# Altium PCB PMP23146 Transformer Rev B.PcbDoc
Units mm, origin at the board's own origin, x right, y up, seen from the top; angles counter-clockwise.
Board outline 35 x 22.3 mm, 6 copper layers (Top Layer, Int1 (Sign), Int2 (Sign), Int3 (Sign), Int4 (Sign), Bottom Layer), stack 2.081 mm thick; 21 components, 16 nets, 60 pads, 32 vias.
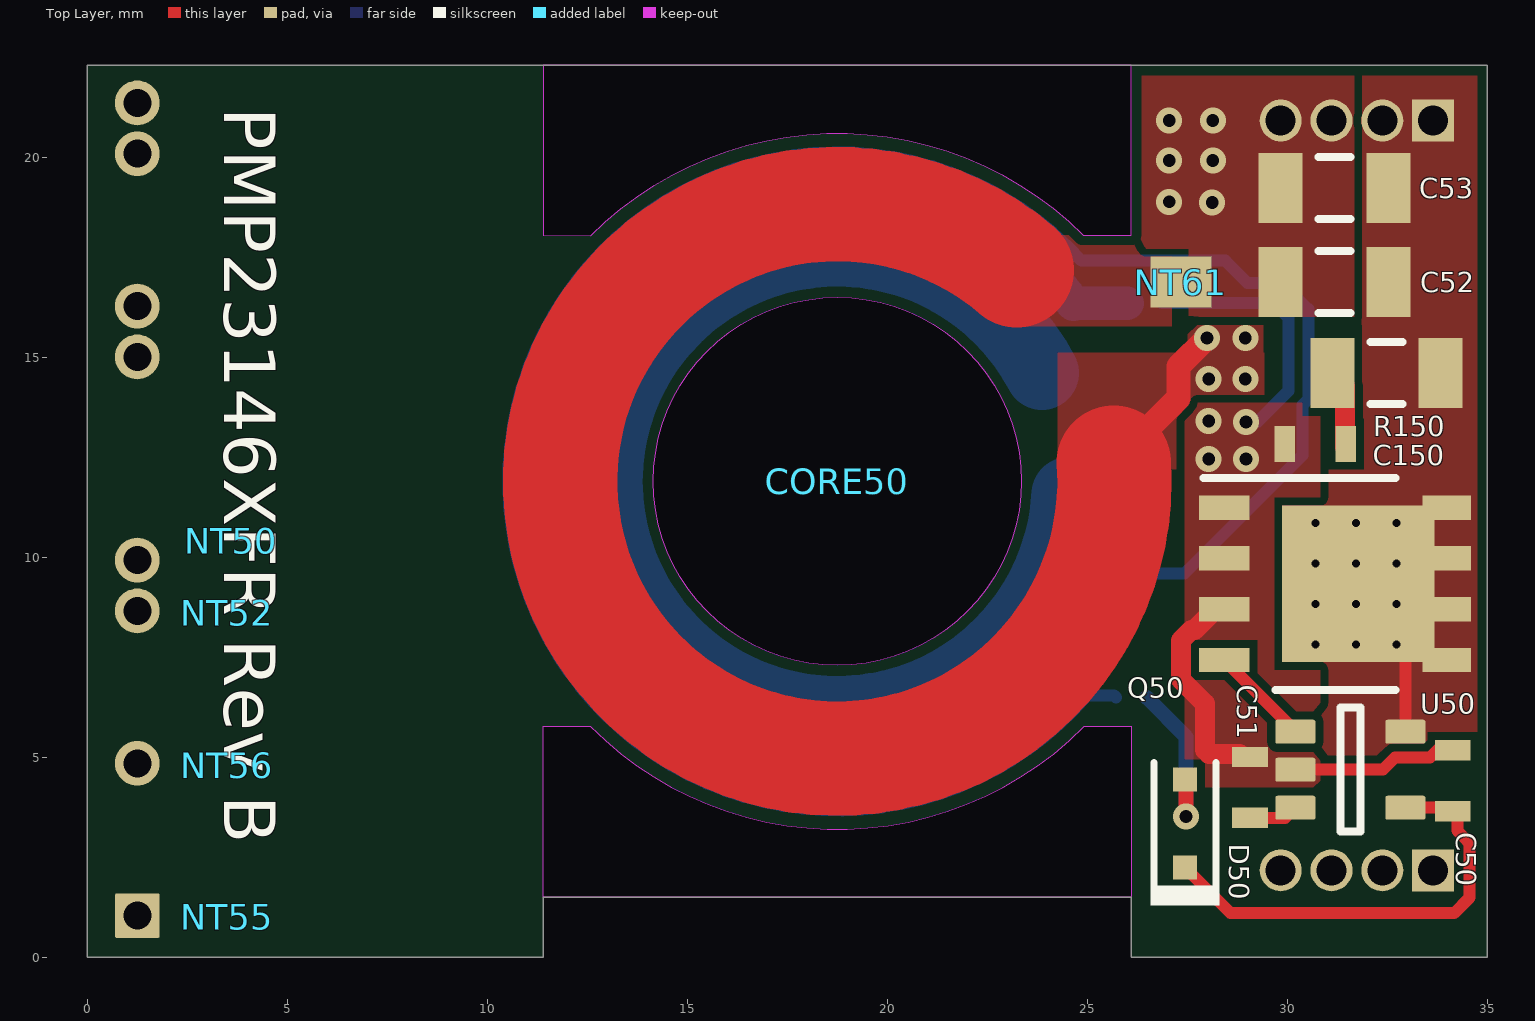
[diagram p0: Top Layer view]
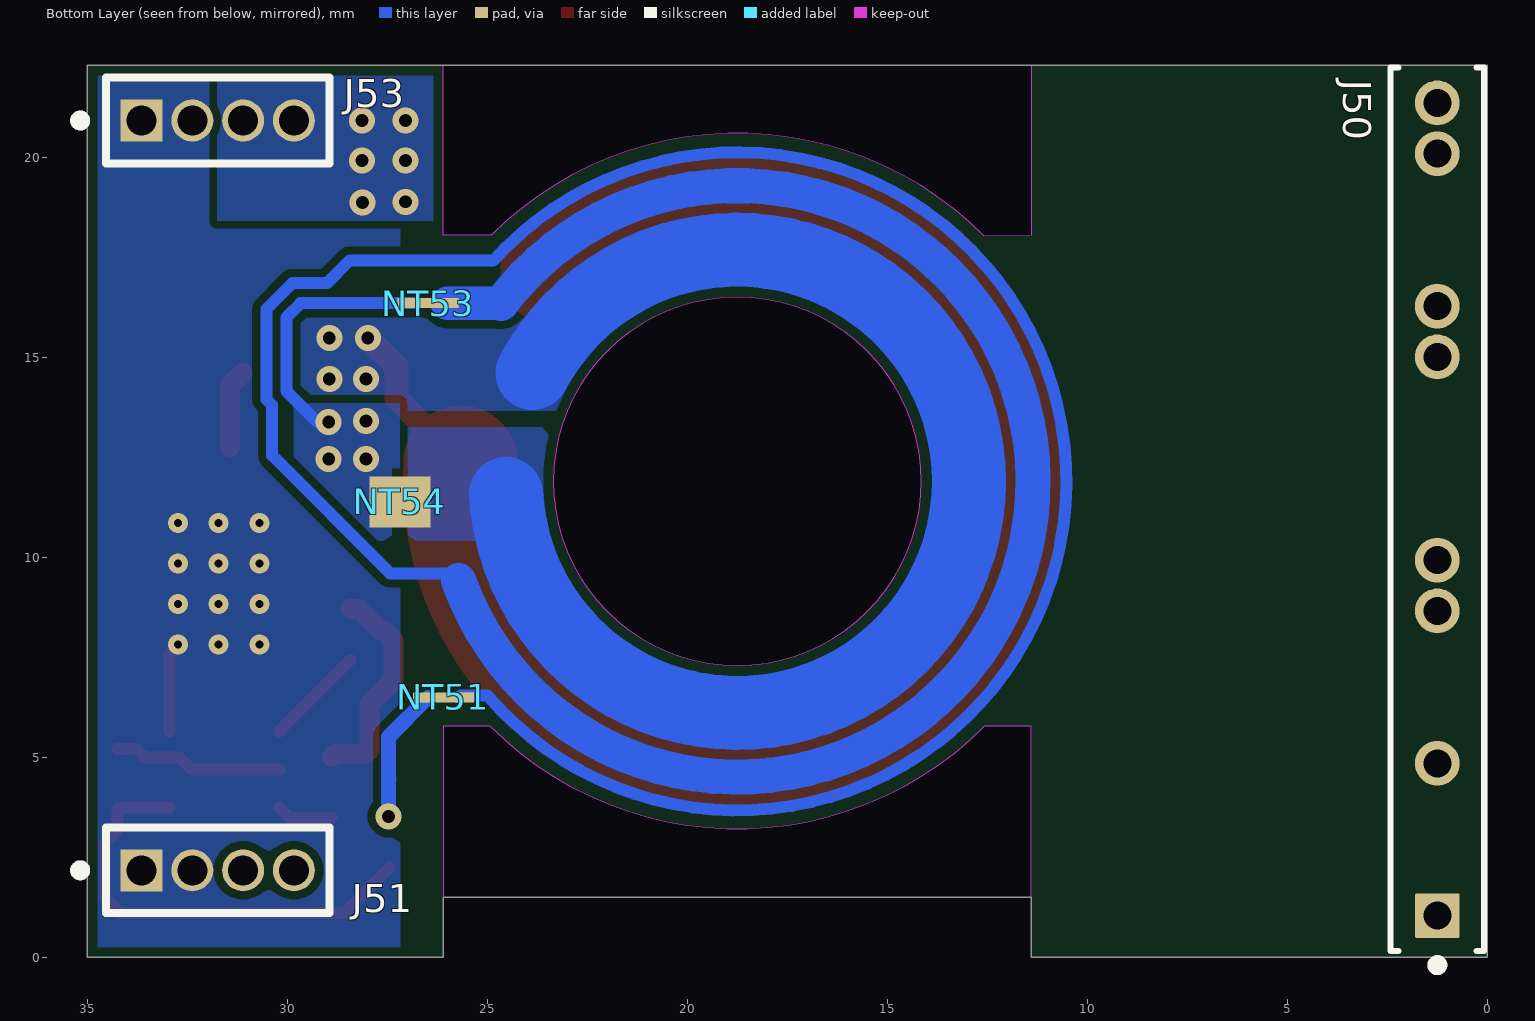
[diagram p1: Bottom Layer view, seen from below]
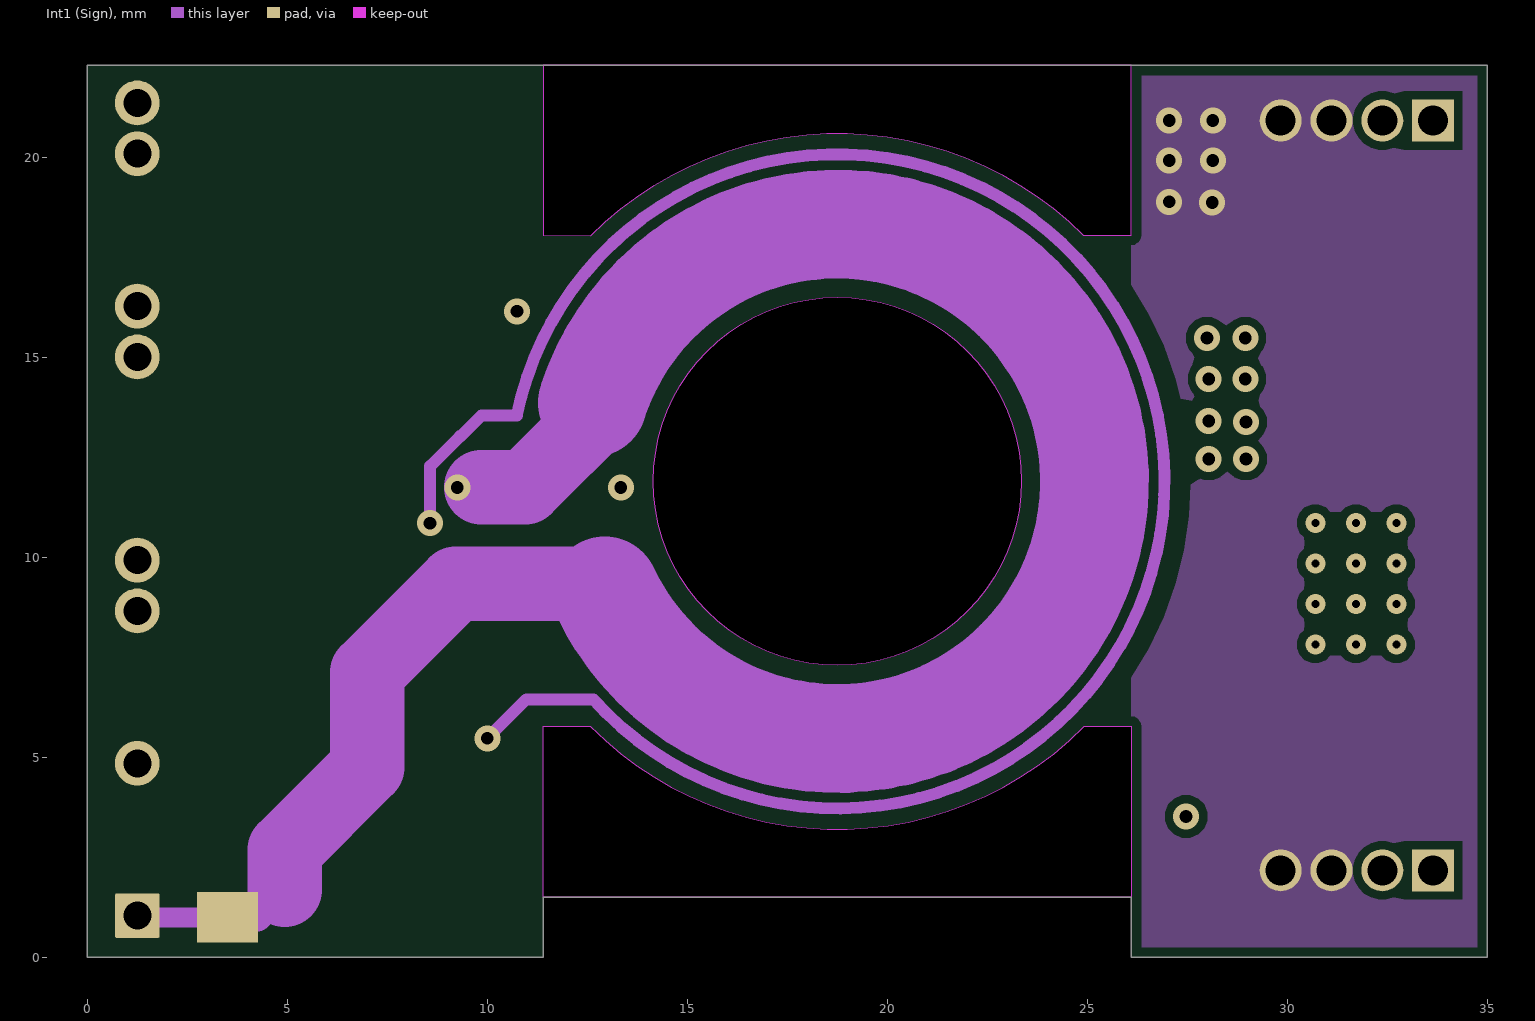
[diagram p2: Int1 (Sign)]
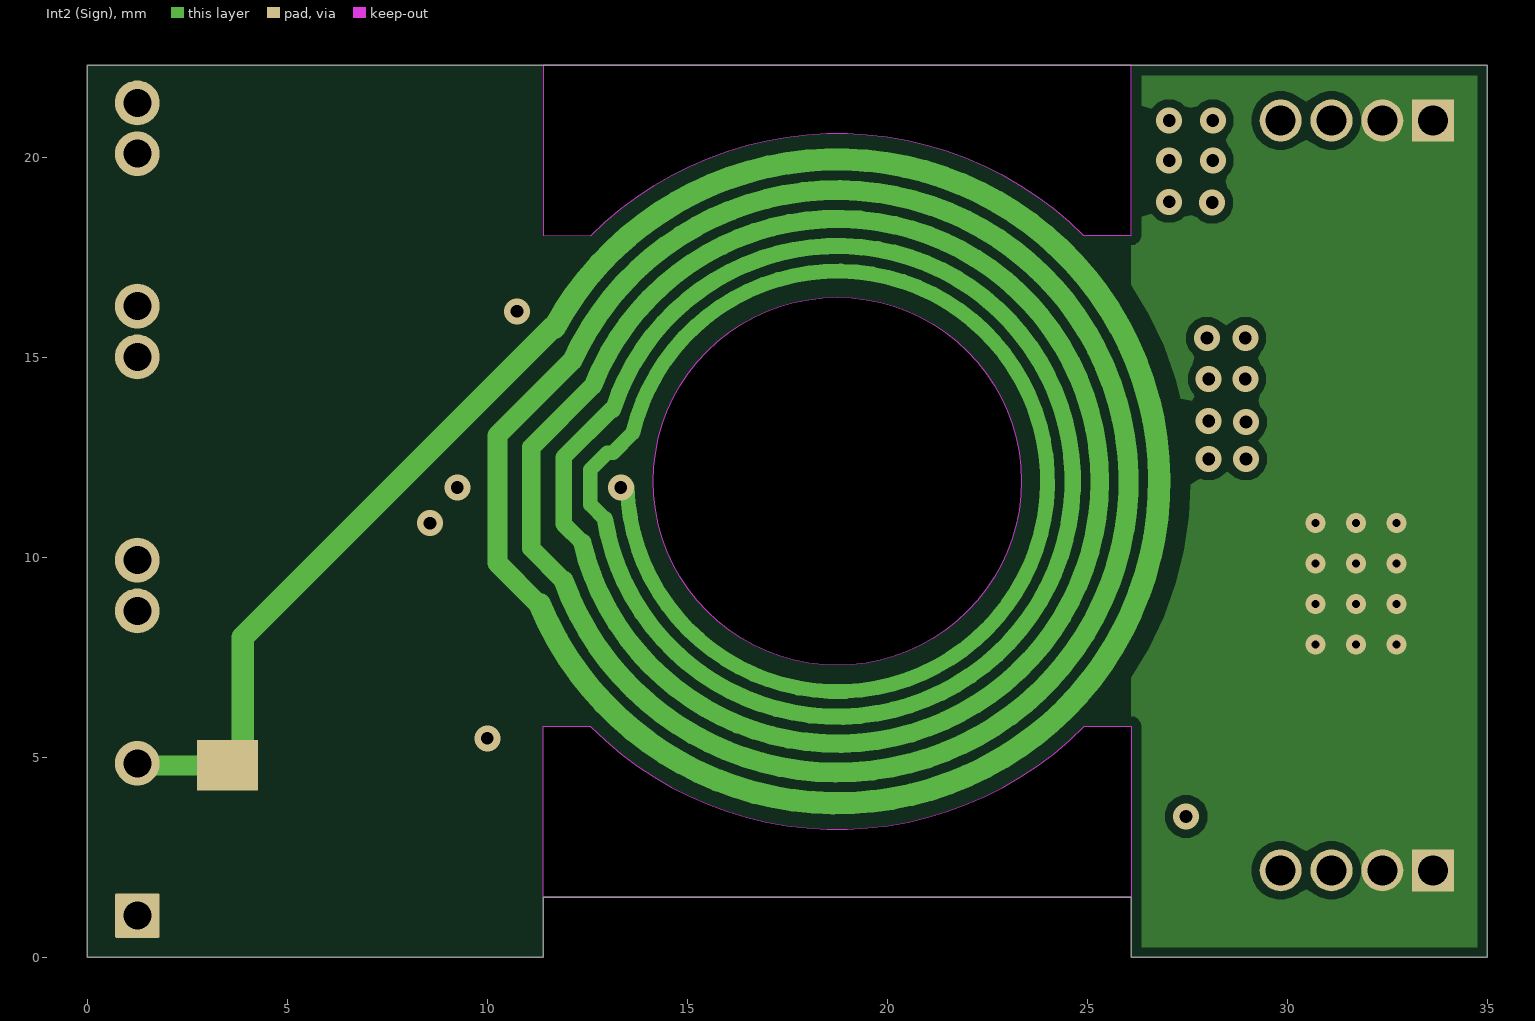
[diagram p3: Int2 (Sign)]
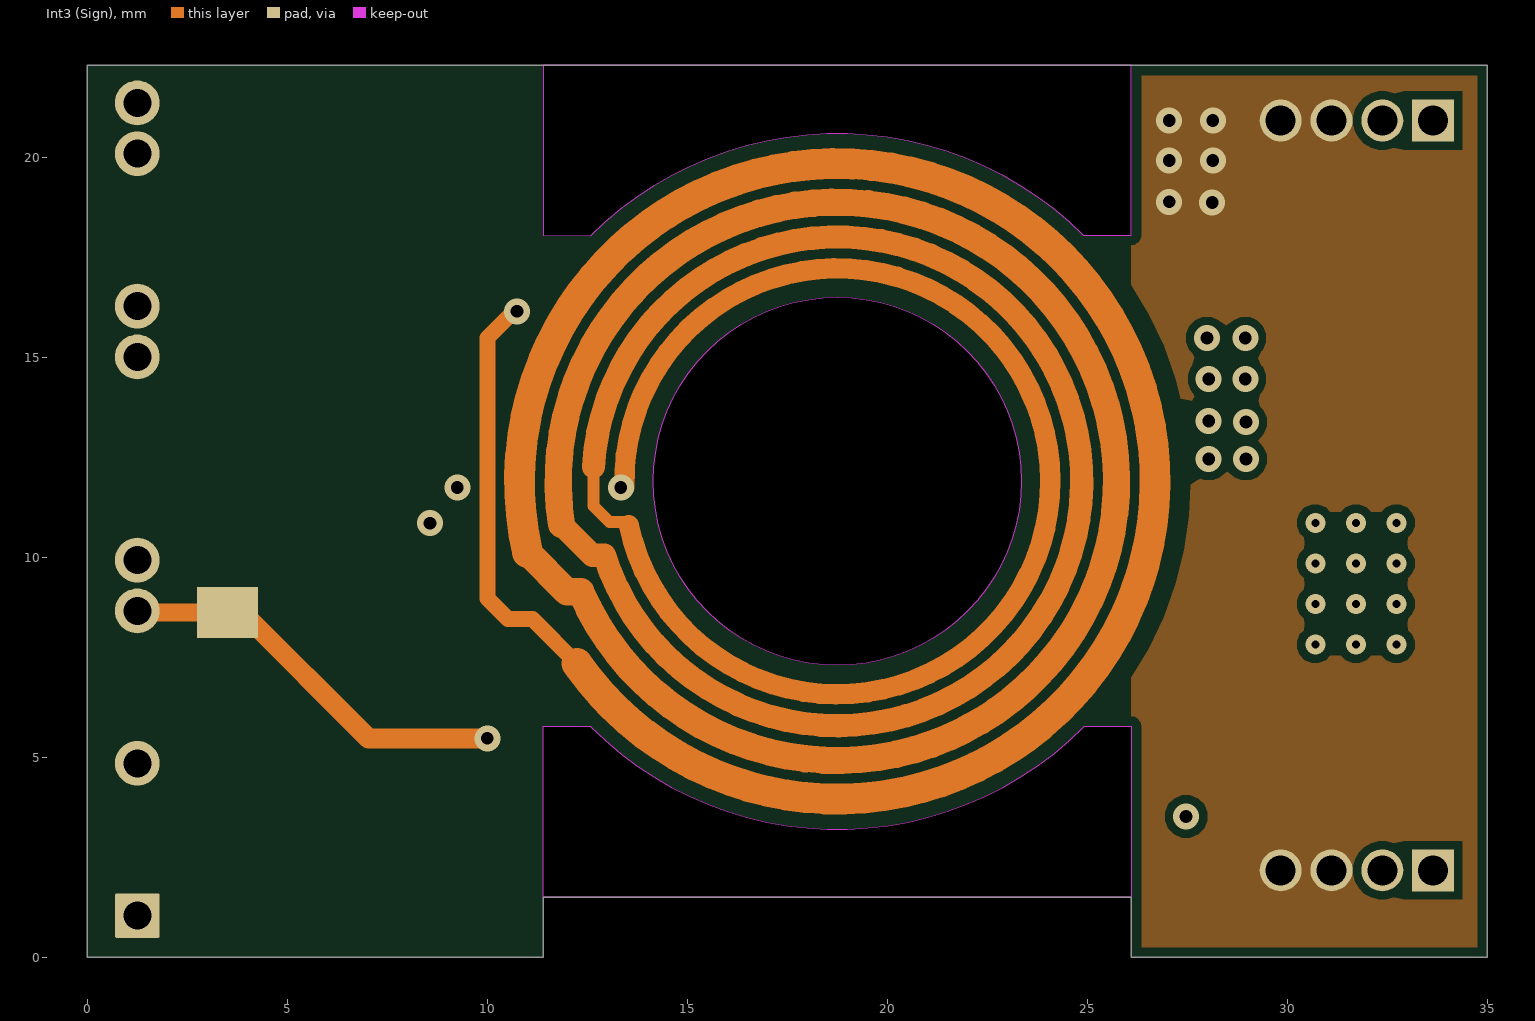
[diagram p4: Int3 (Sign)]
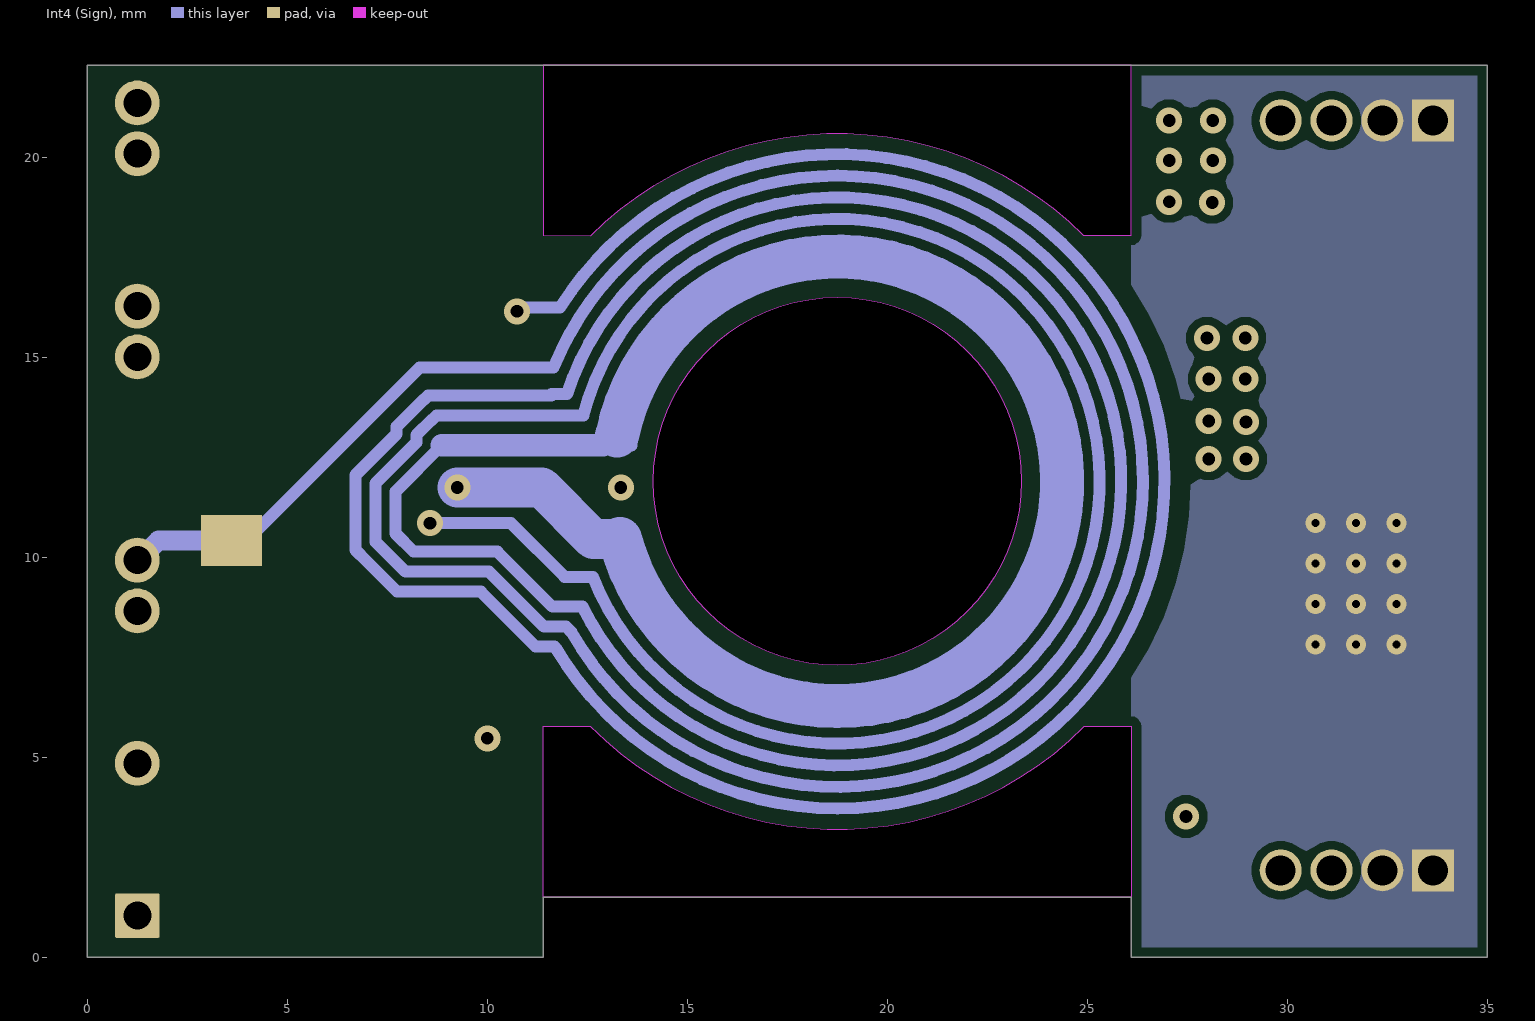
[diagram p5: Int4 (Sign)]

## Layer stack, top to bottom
Top Solder: solder mask 0.0254, SM-001, Dk 4
Top Layer: signal copper 0.07
Dielectric 1: core 0.508, Core-036, Dk 4.6
Dielectric 2: prepreg 0.0584, PP-003, Dk 3.9
Int1 (Sign): signal copper 0.07
Dielectric 3: core 0.1778, Core-022, Dk 4.3
Int2 (Sign): signal copper 0.07
Dielectric 4: prepreg 0.0864, PP-010, Dk 4
Dielectric 5: prepreg 0.0864, PP-010, Dk 4
Int3 (Sign): signal copper 0.07
Dielectric 6: core 0.1778, Core-022, Dk 4.3
Int4 (Sign): signal copper 0.07
Dielectric 7: prepreg 0.0584, PP-003, Dk 3.9
Dielectric 8: core 0.508, Core-036, Dk 4.6
Bottom Layer: signal copper 0.07
Bottom Solder: solder mask 0.0254, SM-001, Dk 4

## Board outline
0,0 0,22.3 35,22.3 35,0 26.1,0 26.1,1.505 11.4,1.505 11.402,0

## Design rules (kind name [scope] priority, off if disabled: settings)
AcuteAngle [All] p1: minimum=5.00000000000000E+0000 checktracksonly=FALSE
AssemblyTestPointUsage [All] p1: valid=2
BoardOutlineClearance BoardOutlineClearance_Pri [InNet('P')] p1: gap=0.4 ignorepadtopadclearanceinfootprint=FALSE
BoardOutlineClearance BoardOutlineClearance_MountingHoles [OnCopper and InComponentClass('Mounting Holes')] p2: gap=0.635 ignorepadtopadclearanceinfootprint=FALSE
BoardOutlineClearance BoardOutlineClearance_Poly [OnCopper and InPoly] p3: gap=0.25 ignorepadtopadclearanceinfootprint=FALSE
BoardOutlineClearance [OnCopper and Not InComponentClass('Logo') and not InComponentClass('FiducialMark') and not InRegion(1000,500,4000,800)] p4: gap=0.25 ignorepadtopadclearanceinfootprint=FALSE
Clearance "Pri To Sec Inner Layers" [InNetClass('Primary') vs InNetClass('Secondary')] p1: gap=0.5 ignorepadtopadclearanceinfootprint=TRUE
Clearance "400V Clearance" [(InNetClass('400V') AND (OnTopLayer Or OnBottomLayer)) vs (InNetClass('Primary LV'))] p2: gap=2.7 ignorepadtopadclearanceinfootprint=FALSE
Clearance Clearance_Keepouts [((IsTrack Or IsArc) And Not InPoly) And IsFree and IsKeepOut vs ((IsTrack Or IsArc) And Not InPoly) And IsFree and IsKeepOut] p3: gap=0 ignorepadtopadclearanceinfootprint=FALSE
Clearance Clearance_Poly [InPolygon] p4: gap=0.203 ignorepadtopadclearanceinfootprint=FALSE except(0: Arc-Hole Track-Hole SMDPad-Hole THPad-Hole Via-Hole Fill-Hole Poly-Hole Region-Hole Text-Hole)
Clearance [All] p5: gap=0.2 ignorepadtopadclearanceinfootprint=TRUE except(0: Arc-Hole Track-Hole SMDPad-Hole THPad-Hole Via-Hole Fill-Hole Poly-Hole Region-Hole Text-Hole)
ComponentClearance ComponentClearance_MountingHoles_FiducialMarks [InComponentClass('Mounting Holes') vs InComponentClass('FiducialMark')] p1: gap=1.27 collisioncheckmode=3 verticalgap=0.254 showdistances=FALSE
ComponentClearance ComponentClearance_Shunt [InComponentClass('Header') vs InComponentClass('Shunt')] p2: gap=0 collisioncheckmode=3 verticalgap=0 showdistances=FALSE
ComponentClearance ComponentClearance_Logo [InComponentClass('Logo')] p3: gap=1.27 collisioncheckmode=3 verticalgap=0.254 showdistances=FALSE
ComponentClearance ComponentClearance_ScrewToNut [(HasFootprint('NY PMS 440 0025 PH')) vs (HasFootprint('Keystone_1902C'))] p4: gap=0.127 collisioncheckmode=3 verticalgap=0.254 showdistances=FALSE
ComponentClearance ComponentClearance_MountingHoles [InComponentClass('Mounting Holes')] p5: gap=6.35 collisioncheckmode=3 verticalgap=2540 showdistances=FALSE
ComponentClearance ComponentClearance_SmallPassives [HasFootprint('0201*') or HasFootprint('0402*') or HasFootprint('0508') or HasFootprint('0603*') or HasFootprint('0612') or HasFootprint('0805*') or HasFootprint('0815*') or HasFootprint('0830*') or HasFootprint('1206*') or HasFootprint('1210*') or HasFootprint('1808*') or HasFootprint('1812*') or HasFootprint('1825*') or HasFootprint('2010*') or HasFootprint('2220*') or HasFootprint('2225*') or HasFootprint('2512*') or HasFootprint('2728*') or HasFootprint('3518*') vs HasFootprint('0201*') or HasFootprint('0402*') or HasFootprint('0508') or HasFootprint('0603*') or HasFootprint('0612') or HasFootprint('0805*') or HasFootprint('0815*') or HasFootprint('0830*') or HasFootprint('1206*') or HasFootprint('1210*') or HasFootprint('1808*') or HasFootprint('1812*') or HasFootprint('1825*') or HasFootprint('2010*') or HasFootprint('2220*') or HasFootprint('2225*') or HasFootprint('2512*') or HasFootprint('2728*') or HasFootprint('3518*')] p6: gap=0.38 collisioncheckmode=3 verticalgap=0.254 showdistances=FALSE
ComponentClearance ComponentClearance_THtoSMT [IsThruComponent vs IsSMTComponent] p7: gap=0.381 collisioncheckmode=3 verticalgap=0.762 showdistances=FALSE
ComponentClearance ComponentClearance_THtoTH [IsThruComponent vs IsThruComponent] p8: gap=0.381 collisioncheckmode=3 verticalgap=0.762 showdistances=FALSE
ComponentClearance [All] p9: gap=0.381 collisioncheckmode=3 verticalgap=0.254 showdistances=FALSE
DiffPairsRouting [All] p1: maxlimit=2.54 minlimit=0.254 mostfreqgap=0.254 toplayer_minwidth=0.381 toplayer_maxwidth=0.381 toplayer_prefwidth=0.381 midlayer1_minwidth=0.381 midlayer1_maxwidth=0.381 midlayer1_prefwidth=0.381 midlayer2_minwidth=0.381 midlayer2_maxwidth=0.381 midlayer2_prefwidth=0.381 midlayer3_minwidth=0.381 midlayer3_maxwidth=0.381 midlayer3_prefwidth=0.381 midlayer4_minwidth=0.381 midlayer4_maxwidth=0.381 midlayer4_prefwidth=0.381 bottomlayer_minwidth=0.381 bottomlayer_maxwidth=0.381 bottomlayer_prefwidth=0.381 maxuncoupledlength=25.4
FabricationTestPointUsage TestPointUsage [All] p1: valid=2 allowmultiple=FALSE
FabricationTestpoint Testpoint [All] p1: side=3 testpointundercomponent=TRUE minsize=1.016 maxsize=2.54 preferedsize=1.524 minholesize=0 maxholesize=1.016 preferedholesize=0.813 testpointgrid=0.025 allowsidetop=TRUE allowsidebottom=TRUE usegrid=TRUE gridtolerance=0
FanoutControl Fanout_LCC [IsLCC] p1: bgadir=Out bgaviamode=Centered fanoutstyle=Auto fanoutdirection=Alternating viagrid=0.025 // Fanout_LCC (Default Rule)
FanoutControl Fanout_BGA [IsBGA] p2: bgadir=Out bgaviamode=Centered fanoutstyle=Auto fanoutdirection=Alternating viagrid=0.025 // Fanout_BGA (Default Rule)
FanoutControl Fanout_Default [All] p4: bgadir=Out bgaviamode=Centered fanoutstyle=Auto fanoutdirection=Alternating viagrid=0.025 // Fanout_Default (Default Rule)
FanoutControl Fanout_Small [(CompPinCount < 5)] p5: bgadir=Out bgaviamode=Centered fanoutstyle=Auto fanoutdirection=OutThenIn viagrid=0.025 // Fanout_Small (Default Rule)
HoleSize [All] p1: absolutevalues=TRUE maxlimit=6.375 minlimit=0.2 maxpercent=80.000 minpercent=20.000
MinimumAnnularRing MinimumAnnularRing_ThermalPadVias [IsVia and InAnyComponent] p1: minimumring=0.15
MinimumAnnularRing [All] p2: minimumring=0.15
MinimumSolderMaskSliver MinimumSolderMaskSliver_Logo [InComponentClass('Logo') vs InComponentClass('Logo')] p1 off: minsoldermaskwidth=0.018
MinimumSolderMaskSliver [All] p2 off: minsoldermaskwidth=0.025
PlaneConnect [All] p1: planeconnectstyle=Direct reliefexpansion=0.254 reliefentries=4 reliefconductorwidth=0.254 reliefairgap=0.254
PolygonConnect [All] p1: connectstyle=Direct reliefconductorwidth=0.381 reliefentries=4 polygonreliefangle="90 Angle" airgapwidth=0.254
RoutingVias ThermalPadVias [IsVia and InAnyComponent] p1: holewidth=0.2 width=0.5 viastyle="Through Hole" minholewidth=0.2 minwidth=0.5 maxholewidth=0.33 maxwidth=0.6
RoutingVias [All] p2: holewidth=0.406 width=0.864 viastyle="Through Hole" minholewidth=0.2 minwidth=0.65 maxholewidth=1.016 maxwidth=1.651
SilkToBoardRegionClearance [Not ((IsComment or IsDesignator) And (Hide <> 'False')) and not InRegion(1000,500,4000,800)] p1:
SilkToSilkClearance SilkToSilkClearance_Pb-FreeLogo [(HasFootprint('Pb-Free_Overlay_Medium') OR HasFootprint('Pb-Free_Overlay_Small')) vs (HasFootprint('Pb-Free_Overlay_Medium') OR HasFootprint('Pb-Free_Overlay_Small'))] p1: silktosilkclearance=0
SilkToSilkClearance [All] p2: silktosilkclearance=0.025
SilkToSolderMaskClearance SilkToComponentPadClearance [IsPad and InAnycomponent] p1: minsilkscreentomaskgap=0 clearancetoexposedcopper=TRUE
SilkToSolderMaskClearance "Silk to Solder Mask Opening" [All] p2: minsilkscreentomaskgap=0 clearancetoexposedcopper=FALSE
SolderMaskExpansion [All] p1: expansion=0.05 istentingtop=FALSE
Width [All] p1: maxlimit=4 minlimit=0.152 preferedwidth=0.254 checkconnectedcopper=TRUE
15 further rules are at their usual default settings.

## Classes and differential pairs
net class Secondary: ISNS S12V
net class Primary: NetNT50_2 NetNT55_2
component class Header: J51 J53

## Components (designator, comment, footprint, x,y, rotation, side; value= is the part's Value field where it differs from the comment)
C50 "GRM188R61E105KA12D" 0603S 34.14,4.415 r90 top value=1uF
C51 "GRM188R61C225KAAD" 0603S 29.067,4.248 r90 top value=2.2uF
C52 "C3216X5R1V226M160AC" 1206_180L 31.175,16.881 r0 top value=22uF
C53 "C3216X5R1V226M160AC" 1206_180L 31.175,19.229 r0 top value=22uF
C150 "GRM1885C2A101JA01D" 0603S 30.699,12.833 r180 top value=100pF
CORE50 "70uH" PCBComponent_1 18.75,11.9 r0 top
D50 "BAS20HT1G" SOD-323 27.44,3.35 r90 top value=200V
J50 "TMS-117-01-L-S" FP-GRPB171VWVN-RC_HDR17-MFG 1.25,11.2 r90 bottom
J51 "TMS-104-01-L-S" Sullins_GRPB041VWVN-RC 31.74,2.175 r180 bottom
J53 "TMS-104-01-L-S" Sullins_GRPB041VWVN-RC 31.74,20.92 r180 bottom
NT50 "Net-Tie" Net-Tie_50milWide_30milLong#1 3.6,10.418 r0 top net-tie
NT51 "Net-Tie" Net-Tie_10milWide_30milLong 26.1,6.498 r180 bottom net-tie
NT52 "Net-Tie" Net-Tie_50milWide_30milLong#2 3.5,8.62 r180 top net-tie
NT53 "Net-Tie" Net-Tie_10milWide_30milLong 26.481,16.355 r0 bottom net-tie
NT54 "Net-Tie" Net-Tie_50milWide_30milLong#3 27.183,11.386 r180 bottom net-tie
NT55 "Net-Tie" Net-Tie_50milWide_30milLong#4 3.5,1 r0 top net-tie
NT56 "Net-Tie" Net-Tie_50milWide_30milLong#5 3.5,4.8 r180 top net-tie
NT61 "Net-Tie" Net-Tie_50milWide_30milLong#3 27.336,16.881 r180 top net-tie
Q50 "FDMS86200" PowerPAK_SO-8 31.207,9.339 r0 top value=100V
R150 "ERJ-8ENF14R0V" 1206L 32.474,14.604 r0 top value=14.0
U50 "UCC24612-1DBVR" DBV0005A_N 31.575,4.69 r0 top

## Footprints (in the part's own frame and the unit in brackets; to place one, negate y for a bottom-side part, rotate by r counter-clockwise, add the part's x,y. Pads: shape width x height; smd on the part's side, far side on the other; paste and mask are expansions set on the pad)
0603S [mil]
  rect 20x35 smd: 1(-30,0) 2(30,0)
  body extent -34,-19 34,19, height 39
1206_180L [mm] "1206_180"
  rect 1.1x1.75 smd: 1(-1.35,0) 2(1.35,0)
  silkscreen extent -0.4,-0.77 0.4,0.77, body extent -1.75,-0.95 1.75,0.95, height 1.8
1206L [mm] "1206 from SM-752 data"
  rect 1.1x1.75 smd: 1(-1.35,0) 2(1.35,0)
  silkscreen extent -0.4,-0.77 0.4,0.77, body extent -1.7,-0.9 1.7,0.9, height 1.35
DBV0005A_N [mm] "SOT23, 5-Leads, Body 2.9x1.6mm, Pitch 0.95mm, Lead Span 2.8mm, IPC Medium Density"
  rrect17% 1x0.6 smd: 1(-1.375,0.95) 2(-1.375,0) 3(-1.375,-0.95) 4(1.375,-0.95) 5(1.375,0.95)
  silkscreen extent -0.25,-1.55 0.25,1.55, body extent -1.42,-1.46 1.42,1.46, height 1.09
FP-GRPB171VWVN-RC_HDR17-MFG [mm]
  rrect9% 1.12x1.12 hole 0.7 paste-1000 mask+0: 1(-10.16,0)
  round 1.12 hole 0.7 paste-1000 mask+0: 4(-6.35,0) 7(-2.54,0) 8(-1.27,0) 12(3.81,0) 13(5.08,0) 16(8.89,0) 17(10.16,0)
  silkscreen extent -11.52,-1.17 11.04,1.17, body extent -10.79,-1.07 10.79,1.07, height 4.4
Net-Tie_10milWide_30milLong [mil] "10mil net tie, no solder mask opening, no solder paste"
  rect 30x10 smd paste-5 mask-5: 1(-15,0) 2(15,0)
Net-Tie_50milWide_30milLong#1 [mil] "50mil net tie, no solder mask opening, no solder paste"
  rect 30x50 on Mid4 paste-20 mask-20: 1(-15,0) 2(15,0)
Net-Tie_50milWide_30milLong#2 [mil] "50mil net tie, no solder mask opening, no solder paste"
  rect 30x50 on Mid3 paste-20 mask-20: 1(-15,0) 2(15,0)
Net-Tie_50milWide_30milLong#3 [mil] "50mil net tie, no solder mask opening, no solder paste"
  rect 30x50 smd paste-20 mask-20: 1(-15,0) 2(15,0)
Net-Tie_50milWide_30milLong#4 [mil] "50mil net tie, no solder mask opening, no solder paste"
  rect 30x50 on Mid1 paste-20 mask-20: 1(-15,0) 2(15,0)
Net-Tie_50milWide_30milLong#5 [mil] "50mil net tie, no solder mask opening, no solder paste"
  rect 30x50 on Mid2 paste-20 mask-20: 1(-15,0) 2(15,0)
PCBComponent_1 [mm]
  Top Layer pour cut-out: 0,-4.6 -1.76,-4.25 -3.253,-3.253 -4.25,-1.76 -4.6,0 -4.6,0 -4.25,1.76 -3.253,3.253 -1.76,4.25 0,4.6 0,4.6 1.76,4.25 3.253,3.253 4.25,1.76 4.6,0 4.6,0 4.25,-1.76 3.253,-3.253 1.76,-4.25 0,-4.6
  Keep-Out Layer board cut-out: -7.348,6.152 -6.164,6.14 -3.341,8.033 -0.009,8.7 3.325,8.039 6.152,6.152 6.152,6.152 7.35,6.152 7.35,10.4 -7.35,10.4
  Keep-Out Layer board cut-out: -7.35,-10.4 -7.35,-6.127 -6.176,-6.127 -3.345,-8.031 0,-8.7 3.345,-8.031 6.176,-6.127 6.176,-6.127 7.35,-6.127 7.35,-10.4
  Keep-Out Layer board cut-out: 0,-4.6 -1.76,-4.25 -3.253,-3.253 -4.25,-1.76 -4.6,0 -4.6,0 -4.25,1.76 -3.253,3.253 -1.76,4.25 0,4.6 0,4.6 1.76,4.25 3.253,3.253 4.25,1.76 4.6,0 4.6,0 4.25,-1.76 3.253,-3.253 1.76,-4.25 0,-4.6
PowerPAK_SO-8 [mil] "Vishay PowerPAK SO-8, Body 5.3x6.0mm (max), Pitch 1.27mm, IPC Medium Density"
  rect 50x24 smd mask+2.99: 1(-109.5,75) 2(-109.5,25) 3(-109.5,-25) 4(-109.5,-75)
  rect 48x24 smd mask+2.99: 5(109.5,-75) 8(109.5,75)
  rect 48x24 smd paste-12 mask+2.99: 6(109.5,-25) 7(109.5,25)
  rect 150x154 smd paste-75 mask+2.99: 9(22.5,0)
  silkscreen extent -130,-104 59,104, body extent -121,-102 121,102, height 43
SOD-323 [mm] "NXP recommended land pattern"
  rect 0.6x0.6 smd paste-0.05: 1(-1.1,0) 2(1.1,0)
  silkscreen extent -2.06,-0.86 1.53,0.86, body extent -1.3,-0.67 1.3,0.68, height 1.1
Sullins_GRPB041VWVN-RC [mm] "TH, Header, 1.27 mm, 4x1, Straight"
  rect 1.05x1.05 hole 0.75: 1(-1.905,0)
  round 1.05 hole 0.75: 2(-0.635,0) 3(0.635,0) 4(1.905,0)
  silkscreen extent -3.54,-1.07 2.79,1.07, body extent -2.79,-1.07 2.79,1.07, height 4.3

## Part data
C50: library part CMP-0007343-5, "CAP, CERM, 1 uF, 25 V, +/- 10%, X5R, 0603", Cap_Case=0603, Manufacturer=MuRata, Supplier Part Number 1=490-3897-1-ND, TempCo=X5R, Tolerance_%=10%, Value1=Unknown, Value2=25V, ValueDisplayed=1uF
C51: library part CMP-0007338-5, "CAP, CERM, 2.2 uF, 16 V, +/- 10%, X5R, 0603", Cap_Case=0603, Manufacturer=MuRata, TempCo=X5R, Tolerance_%=10%, Value1=Unknown, Value2=16V, ValueDisplayed=2.2uF
C52 C53: library part CMP-0008667-2, "CAP, CERM, 22 uF, 35 V, +/- 20%, X5R, 1206", Cap_Case=1206_180, Manufacturer=TDK, Supplier Part Number 1=445-8045-1-ND, TempCo=X5R, Tolerance_%=20%, Value1="0.002398 ohm", Value2=35V, ValueDisplayed=22uF
C150: library part CMP-0007237-4, "CAP, CERM, 100 pF, 100 V, +/- 5%, C0G/NP0, 0603", Cap_Case=0603, Manufacturer=MuRata, Supplier Part Number 1=490-1351-1-ND, TempCo=C0G/NP0, Tolerance_%=5%, Value1=Unknown, Value2=100V, ValueDisplayed=100pF
CORE50: library part Component_1, "EQ20 + I core set, N49 material, gapped to 70uH", Alternate Manufacturer=-, Manufacturer=EPCOS, PartNumber="B66483G0000X149 + B66483K0000X149"
D50: library part CMP-0029150-2, "Diode, Switching, 200 V, 0.2 A, AEC-Q101, SOD-323", Manufacturer="ON Semiconductor", Value1=0.2A, Value2=1.25V
J50: library part CMP-BK1, "Connector Header Through Hole 17 position 0.050\" (1.27mm)", Current_A=1A, Digikey Part Number=GRPB171VWVN-RC-ND, Manufacturer=Samtec, Operating Temperature Range="-40°C to +105°C", Part Number=GRPB171VWVN-RC
J51 J53: library part CMP-0054569-1, "Header, 50mil, 4x1, Gold, TH", Manufacturer=Samtec, Supplier Part Number 1=S9014E-04-ND
NT50 NT52 NT55 NT56: library part CMP-0078142-4, "Single point connection between nets.", Manufacturer=N/A
NT51 NT53 NT54 NT61: library part CMP-0078142-1, "Single point connection between nets.", Manufacturer=N/A
Q50: library part CMP-0000985-1, "MOSFET, N-CH, 150 V, 35 A, PQFN08A", Alternate Manufacturer=None, Manufacturer="Fairchild Semiconductor", Supplier Part Number 1=FDMS86105CT-ND, Value1=0.03, Value2="4.2 nC"
R150: library part CMP-0017368-3, "RES, 14.0, 1%, 0.25 W, AEC-Q200 Grade 0, 1206", Manufacturer=Panasonic, Power_W=250mW, Supplier Part Number 1=P14.0FCT-ND, TempCo="100 ppm/C", Tolerance_%=1%, Value2=0.25W, Value_Code=14R0, ValueDisplayed=14.0
U50: library part CMP-0013050-3, "High-Frequency Multi-Mode Synchronous Rectifier Controller, DBV0005A (SOT-23-5)", Alternate Manufacturer="Texas Instruments", Alternate PartNumber=UCC24612-1DBVT

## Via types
v1: diameter 0.65, hole 0.32, Top Layer to Bottom Layer, 15 vias
v2: diameter 0.5, hole 0.2, Top Layer to Bottom Layer, 12 vias
v3: diameter 0.65, hole 0.32, Int1 (Sign) to Int4 (Sign), 5 vias

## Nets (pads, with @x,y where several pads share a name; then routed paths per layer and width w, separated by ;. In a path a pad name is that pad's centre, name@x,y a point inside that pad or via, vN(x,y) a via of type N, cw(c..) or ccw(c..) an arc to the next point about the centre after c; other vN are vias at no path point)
ISNS: C52.1 C53.1 J51.3 J51.4 J53.3 J53.4 NT61.1
  other v1: 28.121,18.867 27.047,18.889 27.047,19.923 28.137,19.923 27.047,20.92 28.137,20.92
NetC50_1: C50.1 D50.1 U50.4 | length 11.4
  Top Layer w0.3: D50.1 28.585,1.105 34.169,1.105 34.555,1.491 34.555,2.859 34.426,2.988 34.25,3.164 34.25,3.688 34.199,3.74 U50.4
NetC50_2: C50.2 C51.2 C150.2 NT53.2 NT54.1 Q50.1 Q50.2 Q50.3 U50.2 | length 15.9
  Top Layer w0.3: U50.2 32.389,4.69 32.689,4.99 33.565,4.99 33.788,5.212 C50.2@34.25,5.212
  Top Layer w0.5: Q50.3 28.201,8.704 27.685,8.189 27.604,8.189 27.34,7.925 27.34,6.943 27.943,6.34 27.943,5.183 28.044,5.082 28.804,5.082 C51.2@28.877,5.009
  Bottom Layer w0.3: NT53.2 29.667,16.355 30.026,15.996 30.026,14.158 v1@29.25,13.382
  other v1: 28.034,12.456 28.964,12.456 28.964,13.382 28.034,13.406
NetC51_1: C51.1 U50.3 | length 1.4
  Top Layer w0.3: C51.1@28.877,3.485 29.945,3.485 U50.3
NetC150_1: C150.1 R150.1 | length 2
  Top Layer w0.5: R150.1 31.437,14.291 C150.1@31.437,12.755
NetD50_2: D50.2 NT51.1 | length 4.3
  Top Layer w0.37: D50.2 27.47,4.419 v1(27.47,3.523)
  Bottom Layer w0.37: NT51.1 27.47,5.508 v1(27.47,3.523)
NetNT50_2: NT50.2 NT52.1 | length 164
  Int1 (Sign) w0.3: v3(8.567,10.852) 8.567,12.257 8.57,12.26 8.57,12.279 9.32,13.029 9.339,13.029 9.852,13.542 10.736,13.542 ; v3(10,5.476) 10.975,6.451 12.649,6.451 ccw(c18.75,11.9) 10.736,13.542 ; 10.746,13.54 10.738,13.54 10.736,13.542
  Int3 (Sign) w0.5: NT52.1 7.025,5.476 v3(10,5.476)
  Int4 (Sign) w0.3: NT50.2 8.305,14.742 11.658,14.742 cw(c18.75,11.9) 12.105,8.13 11.97,8.265 11.417,8.265 10.043,9.64 7.953,9.64 7.204,10.389 7.204,11.851 8.229,12.876 8.229,13.06 8.598,13.429 8.613,13.429 8.723,13.54 12.398,13.54 cw(c18.75,11.9) 12.64,9.512 11.932,9.512 10.592,10.852 v3(8.567,10.852)
NetNT51_2: NT51.2 NT53.1 | length 96.9
  Bottom Layer w0.3: 25.717,9.421 25.896,9.6 27.432,9.6 30.38,12.548 30.38,13.805 30.526,13.951 30.526,16.203 29.874,16.855 29.008,16.855 28.448,17.415 24.852,17.415 ccw(c18.75,11.9) 24.993,6.546 25.671,6.546 NT51.2
  Bottom Layer w0.84: 24.658,16.355 NT53.1@26,16.355
  Bottom Layer w0.88: 24.654,16.352 ccw(c18.75,11.9) 25.717,9.421
NetNT54_2: NT54.2 NT61.2 | length 76.1
  Top Layer w0.37: 25.664,12.367 25.664,13.158
  Top Layer w0.6: 25.664,12.367 27.274,13.976 27.274,14.768 v1(27.989,15.483)
  Top Layer w2.86: 23.24,17.179 ccw(c18.75,11.9) 25.664,12.367
  Bottom Layer w1.85: 23.87,14.604 ccw(c18.75,11.9) 24.531,11.584
  other v1: 28.034,14.461 28.95,14.461 28.95,15.483
NetNT55_2: NT55.2 NT56.1 | length 595.6
  Int1 (Sign) w0.5: NT55.2 NT55.2@4.25,1
  Int1 (Sign) w0.7: NT55.2@4.25,1 4.935,1.685
  Int1 (Sign) w1.86: 4.935,1.685 4.935,2.685 7,4.75 7,7.129 9.21,9.339 13.324,9.339 ; 9.85,11.749 10.95,11.749 12.935,13.735 13.037,13.735
  Int1 (Sign) w2.72: 12.628,13.866 cw(c18.75,11.9) 12.935,9.155
  Int2 (Sign) w0.37: 12.941,10.956 12.574,11.324 12.574,12.189 13,12.616 13.142,12.616 13.636,13.11 cw(c18.75,11.9) v3@13.497,11.748 ; v3@13.225,11.748 13.334,11.748 v3(13.336,11.749)
  Int2 (Sign) w0.41: 12.371,10.37 11.907,10.834 11.907,12.5 13.092,13.685 13.142,13.685 cw(c18.75,11.9) 12.941,10.956
  Int2 (Sign) w0.46: 11.907,9.416 11.1,10.222 11.1,12.751 12.642,14.292 cw(c18.75,11.9) 12.371,10.37
  Int2 (Sign) w0.5: 11.312,8.822 11.289,8.822 10.25,9.861 10.25,13.044 12.126,14.92 cw(c18.75,11.9) 11.907,9.416
  Int2 (Sign) w0.56: NT56.1 3.881,8 11.614,15.733 ; 11.312,8.822 ccw(c18.75,11.9) 11.671,15.733
  Int3 (Sign) w0.3: v3@10.667,16.15 v3(10.746,16.15) ; 12.651,12.267 12.651,11.286 13.049,10.888 13.459,10.888 13.538,10.809
  Int3 (Sign) w0.4: v3@10.667,16.15 10,15.483 10,8.975 10.523,8.452 11.132,8.452 12.242,7.343
  Int3 (Sign) w0.51: v3@13.427,11.752 cw(c18.75,11.9) 13.538,10.809
  Int3 (Sign) w0.58: 11.853,10.825 12.628,10.051 12.927,10.051 ccw(c18.75,11.9) 12.651,12.267
  Int3 (Sign) w0.68: 11.006,10.123 11.99,9.14 12.339,9.14 ccw(c18.75,11.9) 11.853,10.825
  Int3 (Sign) w0.77: 11.006,10.123 cw(c18.75,11.9) 12.242,7.343
  Int4 (Sign) w0.3: 8.859,12.799 7.704,11.644 7.704,10.596 8.16,10.14 10.25,10.14 11.625,8.765 12.38,8.765 ccw(c18.75,11.9) 11.996,14.089 11.605,14.089 11.605,14.04 8.516,14.04 8.406,13.929 8.391,13.929 7.729,13.267 7.729,13.084 6.704,12.058 6.704,10.182 6.986,9.899 7.182,9.704 7.482,9.404 7.746,9.14 9.836,9.14 11.21,7.765 11.68,7.765 11.71,7.735 ccw(c18.75,11.9) 11.822,16.249 10.845,16.249 v3(10.746,16.15) ; 12.895,12.799 12.904,12.79 13.607,12.79
  Int4 (Sign) w0.56: 8.859,12.799 12.895,12.799
  Int4 (Sign) w1: v3(9.25,11.748) 11.359,11.748 12.651,10.456 13.319,10.456
  Int4 (Sign) w1.1: 13.248,13.044 cw(c18.75,11.9) 13.319,10.456
NetQ50_4: Q50.4 U50.1 | length 2.5
  Top Layer w0.3: Q50.4 30.2,5.659 U50.1
PWRGND: J50.7 NT52.2 | length 1.9
  Int3 (Sign) w0.46: J50.7@1.25,8.62 NT52.2
S12V: C52.2 C53.2 J51.1 J51.2 J53.1 J53.2 Q50.5 Q50.6 Q50.7 Q50.8 Q50.9 R150.2 U50.5 | length 2.3
  Top Layer w0.3: v2(32.731,7.815) 32.95,7.596 U50.5
  other v2: 30.699,7.815 31.715,7.815 30.699,8.831 31.715,8.831 32.731,8.831 30.699,9.847 31.715,9.847 32.731,9.847 30.699,10.863 31.715,10.863 32.731,10.863
VAUX: J50.8 NT50.1 | length 2.1
  Int4 (Sign) w0.5: J50.8@1.25,9.89 1.778,10.418 NT50.1@3.119,10.418
VDCIN: J50.1 NT55.1 | length 1.9
  Int1 (Sign) w0.5: J50.1@1.25,1 NT55.1
VSWN: J50.4 NT56.2 | length 1.9
  Int2 (Sign) w0.5: J50.4@1.26,4.8 NT56.2
  Int2 (Sign) w0.7: J50.4@1.25,4.81 J50.4@1.26,4.8
pads on no net: J50.12 J50.13 J50.16 J50.17

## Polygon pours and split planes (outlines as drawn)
NetC50_2 on Top Layer "TOP_LAYER_NETC50_2_P000" (solid, remove dead copper, pour order 0): 27.432,4.247 30.824,4.247 30.824,13.86 27.432,13.86
NetNT54_2 on Top Layer "TOP_LAYER_NETNT54_2_P014" (solid, remove dead copper, pour order 14): 27.505,13.108 29.398,13.108 29.398,15.907 27.505,15.907
NetNT54_2 on Top Layer "TOP_LAYER_NETNT54_2_P005" (solid, remove dead copper, pour order 5): 23.041,15.782 27.114,15.782 27.114,18.052 23.041,18.052
S12V on Top Layer "TOP_LAYER_S12V_P009" (solid, remove dead copper, pour order 9): 29.067,4.248 35,4.248 35,22.3 29.067,22.3
ISNS on Top Layer "TOP_LAYER_ISNS_P001" (solid, remove dead copper, pour order 1): 26.184,16.011 31.671,16.011 31.671,22.3 26.184,22.3
NetNT54_2 on Top Layer "TOP_LAYER_NETNT54_2_P006" (solid, remove dead copper, pour order 6): 24.262,12.204 29.42,12.204 29.42,15.116 24.262,15.116
ISNS on Bottom Layer "BOTTOM_LAYER_ISNS_P007" (solid, remove dead copper, pour order 7): 26.1,18.419 31.75,18.419 31.75,22.3 26.1,22.3
S12V on Bottom Layer "BOTTOM_LAYER_12VSA_P008" (solid, remove dead copper, pour order 8): 27.171,0 35.142,0 35.142,22.3 27.171,22.3
NetC50_2 on Bottom Layer "BOTTOM_LAYER_NETC50_2_P002" (solid, remove dead copper, pour order 2): 27.193,10.418 29.835,10.418 29.835,13.854 27.193,13.854
NetNT54_2 on Bottom Layer "BOTTOM_LAYER_NETNT54_2_P004" (solid, remove dead copper, pour order 4): 23.408,10.418 27.183,10.418 27.183,13.247 23.408,13.247
NetNT54_2 on Bottom Layer "BOTTOM_LAYER_NETNT54_2_P003" (solid, remove dead copper, pour order 3): 23,13.66 29.778,13.66 29.778,16.043 23,16.043
ISNS on Int1 (Sign) "INT1_(SIGN)_ISNS_P010" (solid, remove dead copper, pour order 10): 26.1,0 35,0 35,22.3 26.1,22.3
S12V on Int2 (Sign) "INT2_(SIGN)_12VSA_P011" (solid, remove dead copper, pour order 11): 26.1,0 34.906,0 34.906,22.3 26.1,22.3
ISNS on Int3 (Sign) "INT3_(SIGN)_ISNS_P012" (solid, remove dead copper, pour order 12): 26.1,0 34.906,0 34.906,22.3 26.1,22.3
S12V on Int4 (Sign) "INT4_(SIGN)_12VSA_P013" (solid, remove dead copper, pour order 13): 26.1,0 35,0 35,22.3 26.1,22.3

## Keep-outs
Keep-Out Layer:
  text ".Layer_Name" at 14.656,-21.806 h1.52

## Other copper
Top Layer:
  text ".Layer_Name" at 14.656,-21.806 h1.52
Bottom Layer:
  text ".Layer_Name" at 14.656,-21.806 h1.52

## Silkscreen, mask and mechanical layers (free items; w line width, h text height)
Top Overlay:
  text "PMP23146XFR Rev B" at 3,21.25 h2.2 r270
  text ".Layer_Name" at 14.656,-21.806 h1.52
Bottom Overlay:
  text ".Layer_Name" at 14.656,-21.806 h1.52
Top Paste:
  text ".Layer_Name" at 14.656,-21.806 h1.52
Bottom Paste:
  text ".Layer_Name" at 14.656,-21.806 h1.52
Top Solder:
  text ".Layer_Name" at 14.656,-21.806 h1.52
  text ".Layer_Name" at 14.656,-21.806 h1.52
Bottom Solder:
  text ".Layer_Name" at 14.656,-21.806 h1.52
Drill Guide:
  text ".Layer_Name" at 14.656,-21.806 h1.52
M1 Board Outline:
  the board outline again, w0.254
  text ".Layer_Name" at 14.656,-21.806 h1.52
M2 Board Dimensions:
  rectangle: 0,-6.985 3.175,-3.81
  rectangle: 3.175,-10.16 12.7,-6.985
  lines w0.178: 0,-6.985 25.4,-6.985 ; 3.175,-10.16 3.175,-3.81 ; 6.35,-10.16 6.35,-3.81 ; 12.7,-10.16 12.7,-3.81 ; 19.05,-10.16 19.05,-3.81 ; 0,-10.16 25.4,-10.16 25.4,-3.81 0,-3.81 0,-10.16
  text ".Layer_Name" at 14.656,-21.806 h1.52
M3 3D STEP Top:
  text ".Layer_Name" at 14.656,-21.806 h1.52
M4 3D STEP Bottom:
  text ".Layer_Name" at 14.656,-21.806 h1.52
M5 Assembly Top:
  lines w0.254: -7.417,-23.626 160.223,-23.626 ; -7.417,-18.462 160.274,-18.462 ; -7.417,-13.297 -7.417,-28.791 94.31,-28.791 160.274,-28.791 160.274,-13.297 -7.404,-13.297 -7.404,-28.791 32.614,-28.791 ; 55.194,-28.791 55.194,-13.297 ; 87.376,-18.462 87.376,-13.297 ; 108.712,-18.462 108.712,-13.297 ; 124.511,-28.956 124.511,-23.804
  text "COMPONENTS MARKED 'DNP' SHOULD NOT BE POPULATED." at 29.299,-8.09 h1.52
  text "ASSEMBLY VARIANT:" at 29.286,-11.024 h1.52
  text ".VariantName" at 55.601,-11.024 h1.52
  text "PCB VIEWED FROM TOP SIDE" at -5.804,-16.654 h1.52
  text "BOARD #:" at 57.099,-16.654 h1.52
  text ".PRJ_Number" at 70.955,-16.654 h1.52
  text "REV:" at 92.405,-16.654 h1.52
  text ".PCB_Rev" at 99.809,-16.654 h1.52
  text "SVN REV:" at 113.69,-16.654 h1.52
  text ".VersionControl_RevNumber" at 126.543,-16.654 h1.52
  text "TID #:" at 57.099,-21.819 h1.52
  text ".TID" at 70.955,-21.819 h1.52
  text "PLOT NAME =" at -5.804,-27.034 h1.52
  text ".plot_File_Name" at 14.656,-27.034 h1.52
  text "GENERATED    :" at 57.15,-27.034 h1.52
  text ".Print_Date" at 79.235,-27.034 h1.52
  text ".Print_Time" at 97.752,-27.034 h1.52
  text "TEXAS INSTRUMENTS" at 129.87,-27.034 h1.52
M6 Assembly Bottom:
  lines w0.254: -7.429,-18.474 160.261,-18.474 ; -7.379,-23.639 160.261,-23.639 ; 28.334,-28.969 28.334,-23.817 ; 44.133,-18.474 44.133,-13.31 ; 65.468,-18.474 65.468,-13.31 ; 97.65,-28.804 97.65,-13.31 ; 120.231,-28.804 160.249,-28.804 160.249,-13.31 -7.429,-13.31 -7.429,-28.804 58.534,-28.804 160.261,-28.804 160.261,-13.31
  text "COMPONENTS MARKED 'DNP' SHOULD NOT BE POPULATED." at 154.991,-8.077 h1.52
  text ".VariantName" at 128.473,-11.024 h1.52
  text "ASSEMBLY VARIANT:" at 154.864,-11.024 h1.52
  text ".VersionControl_RevNumber" at 26.302,-16.667 h1.52
  text "SVN REV:" at 39.154,-16.667 h1.52
  text ".PCB_Rev" at 53.035,-16.667 h1.52
  text "REV:" at 60.439,-16.667 h1.52
  text ".PRJ_Number" at 81.89,-16.667 h1.52
  text "BOARD #:" at 95.745,-16.667 h1.52
  text "PCB VIEWED FROM BOTTOM SIDE" at 158.648,-16.667 h1.52
  text ".TID" at 81.89,-21.831 h1.52
  text "TID #:" at 95.745,-21.831 h1.52
  text "TEXAS INSTRUMENTS" at 22.974,-27.047 h1.52
  text ".Print_Time" at 55.093,-27.047 h1.52
  text ".Print_Date" at 73.609,-27.047 h1.52
  text "GENERATED    :" at 95.694,-27.047 h1.52
  text ".plot_File_Name" at 138.189,-27.047 h1.52
  text "PLOT NAME =" at 158.648,-27.047 h1.52
M9 Title Sheet:
  drawing of 57 lines, arcs and shapes, not listed
  text "1" at 18.792,204.127 h1.78
  text "2" at 82.182,204.127 h1.78
  text "3" at 145.411,204.127 h1.78
  text "4" at 209.08,204.127 h1.78
  text "5" at 272.555,204.127 h1.78
  text "6" at 336.182,204.127 h1.78
  text "A" at -10.579,175.095 h1.78
  text "A" at 365.341,175.095 h1.78
  text "B" at -10.579,114.643 h1.78
  text "B" at 365.341,114.643 h1.78
  text "C" at -10.579,54.318 h1.78
  text "C" at 365.341,54.318 h1.78
  text "PROJECT TITLE:" at 288.125,7.048 h1.14
  text ".PRJ_Title" at 289.395,3.662 h1.78
  text "DESIGNED FOR:" at 288.125,-0.597 h1.14
  text ".PRJ_Customer" at 289.395,-4.153 h1.78
  text "D" at -10.579,-5.88 h1.78
  text "D" at 365.341,-5.88 h1.78
  text "FILE NAME:" at 288.125,-8.217 h1.14
  text ".PCB_File_Name_No_Path" at 289.395,-11.265 h1.78
  text "Texas Instruments (TI) and/or its licensors do not warrant the accuracy or completeness of this specification" at 161.9,-15.376 h1.14
  text "ENGINEER:" at 288.125,-15.583 h1.14
  text "LAYOUT BY:" at 326.352,-15.583 h1.14
  text "or any information contained therein. TI and/or its licensors do not warrant that this design will meet" at 160.757,-18.237 h1.14
  text ".PRJ_Engineer" at 289.395,-19.52 h1.78
  text ".PCB_Layout" at 327.635,-19.52 h1.78
  text "the specifications, will be suitable for your application or fit for any particular purpose, or will operate in" at 160.757,-21.099 h1.14
  text ".Layer_Name" at 14.656,-21.806 h1.52
  text "ALTIUM DESIGNER VERSION:" at 326.352,-23.457 h1.14
  text "an implementation. TI and/or its licensors do not warrant that the design is production worthy. You should" at 160.757,-23.961 h1.14
  text "completely validate and test your design implementation to confirm the system functionality for your application." at 161.9,-26.822 h1.14
  text ".print_Scale" at 289.395,-26.843 h1.78
  text ".Application_BuildNumber" at 327.635,-26.843 h1.78
  text "1" at 18.792,-32.093 h1.78
  text "2" at 82.182,-32.093 h1.78
  text "3" at 145.411,-32.093 h1.78
  text "4" at 209.08,-32.093 h1.78
  text "5" at 272.555,-32.093 h1.78
  text "6" at 336.182,-32.093 h1.78
M10 Fab Notes:
  drawing of 189 lines, arcs and shapes, not listed
  text "DESIGN INFORMATION" at 314.503,161.447 h1.52
  text "MIN. TRACK WIDTH:" at 298.131,158.091 h1.52
  text "8" at 325.976,158.091 h1.52
  text "MIL" at 329.907,158.091 h1.52
  text "7.874" at 321.75,155 h1.52
  text "MIN. CLEARANCE:" at 298.131,154.938 h1.52
  text "MIL" at 329.907,154.938 h1.52
  text "MIN. VIA PAD SIZE:" at 298.131,151.785 h1.52
  text "24" at 325.214,151.785 h1.52
  text "MIL" at 329.907,151.785 h1.52
  text "0.05mm (2MIL)" at 315.784,148.486 h1.52
  text "MINIMUM ANNULAR RING" at 289.769,148.277 h1.52
  text "EXTERNAL" at 333.768,148.277 h1.52
  text "PER" at 294.849,145.48 h1.52
  text "IPC-D-275 CLASS 2 LEVEL C" at 300.437,145.48 h1.52
  text "MIL, HOLES" at 338.238,142.928 h1.52
  text "+/-" at 328.27,142.709 h1.52
  text "+/-" at 349.961,142.709 h1.52
  text "REGISTRATION TOLERANCES:" at 289.769,142.682 h1.52
  text "METAL" at 320.243,142.682 h1.52
  text "5" at 334.879,142.683 h1.52
  text "3" at 356.037,142.683 h1.52
  text "MIL" at 358.99,142.682 h1.52
  text "HOLE SIZE TOLERANCE (UNLESS OTHERWISE SPECIFIED):" at 289.769,140.185 h1.52
  text "+/-" at 349.961,140.112 h1.52
  text "3" at 356.037,140.085 h1.52
  text "MIL" at 358.99,140.085 h1.52
  text "MATERIAL:" at 287.87,136.589 h1.52
  text "FR-4 High Tg" at 312.926,133.324 h1.52
  text "X" at 309.257,133.122 h1.52
  text "FR-408" at 298.563,133.007 h1.52
  text "OTHER" at 336.358,133.007 h1.52
  text "62 MIL (1.6mm) +/-10%" at 306.694,129.374 h1.52
  text "X" at 303.643,129.312 h1.52
  text "THICKNESS:" at 289.769,129.165 h1.52
  text "OTHER" at 339.33,129.165 h1.52
  text "TOLERANCE:" at 289.769,125.652 h1.52
  text "X" at 311.314,125.652 h1.52
  text "ANSI IPC-6012 TYPE 3 CLASS 2" at 315.836,125.652 h1.52
  text "OTHER +/-" at 315.835,121.989 h1.52
  text "BOW & TWIST:" at 289.769,118.302 h1.52
  text "X" at 311.314,118.302 h1.52
  text "ANSI IPC-6012 TYPE 3 CLASS 2" at 315.836,118.302 h1.52
  text "OTHER +/-" at 315.835,114.576 h1.52
  text "DRILLING:" at 287.87,111.258 h1.52
  text "NC_DRILL FILES" at 332.599,108.586 h1.52
  text "REFERENCE:" at 289.769,108.486 h1.52
  text "X" at 306.463,108.484 h1.52
  text "AS SHOWN" at 310.984,108.486 h1.52
  text "X" at 329.348,108.486 h1.52
  text "OTHER" at 340.168,104.873 h1.52
  text "PTH COPPER THICKNESS:" at 289.761,104.783 h1.52
  text "X" at 318.697,104.783 h1.52
  text "20-30 um" at 321.948,104.783 h1.52
  text "BOARD FINISH:" at 287.87,101.034 h1.52
  text "SILKSCREEN:" at 291.812,98.237 h1.52
  text "X" at 316.14,98.237 h1.52
  text "TOP" at 319.112,98.237 h1.52
  text "X" at 329.094,98.237 h1.52
  text "BOTTOM" at 332.091,98.237 h1.52
  text "SILKSCREEN COLOR:" at 291.812,94.295 h1.52
  text "X" at 316.115,94.295 h1.52
  text "WHITE" at 319.112,94.295 h1.52
  text "OTHER" at 332.091,94.295 h1.52
  text "X" at 319.442,90.652 h1.52
  text "GREEN" at 322.439,90.652 h1.52
  text "OTHER" at 338.136,90.652 h1.52
  text "SOLDER RESIST COLOR:" at 291.812,90.477 h1.52
  text "X" at 319.442,86.734 h1.52
  text "MATTE" at 322.439,86.734 h1.52
  text "SEMI-GLOSS" at 338.125,86.717 h1.52
  text "IMMERSION GOLD (ENIG)" at 314.819,82.345 h1.52
  text "ENEPIG" at 348.793,82.162 h1.52
  text "SURFACE FINISH:" at 287.87,82.136 h1.52
  text "X" at 310.298,82.136 h1.52
  text "IMM. TIN/SILVER OR EQUIV" at 296.24,78.649 h1.52
  text "OTHER" at 332.599,78.549 h1.52
  text "ARRAY/PANEL:" at 287.87,74.602 h1.52
  text "CUT AND TRIM PER M1 BOARD OUTLINE" at 314.819,74.393 h1.52
  text "N.C. ROUTE" at 314.819,70.94 h1.52
  text "X" at 332.295,70.94 h1.52
  text "V. SCORE" at 336.816,70.94 h1.52
  text "CERTIFICATION:" at 287.87,67.66 h1.52
  text "MATERIALS AND WORKMANSHIP FOR ALL PCBS" at 306.285,67.66 h1.52
  text "TO MEET OR EXCEED THE REQUIREMENTS OF:" at 306.285,65.271 h1.52
  text "X" at 297.078,62.003 h1.52
  text "ANSI IPC-A-600F CLASS ->" at 300.329,62.003 h1.52
  text "X" at 342.188,62.003 h1.52
  text "2" at 344.982,62.003 h1.52
  text "1" at 336.981,61.965 h1.52
  text "3" at 353.973,61.965 h1.52
  text "X" at 317.702,58.252 h1.52
  text "RoHS" at 320.953,58.252 h1.52
  text "OTHER" at 337.321,58.252 h1.52
  text "PER ORDER" at 347.407,58.252 h1.52
  text "ALL BOARDS MUST MEET OR EXCEED UL94-V0 REQUIREMENTS." at 288.569,54.345 h1.52
  text "PCB MUST BEAR THE UL94V-0 UL REGISTERED MATERIAL ID NUMBER" at 288.569,51.397 h1.52
  text "ADDITIONAL REQUIREMENTS:" at 287.87,47.094 h1.52
  text "MICROSECTION:" at 289.769,44.373 h1.52
  text "YES" at 312.775,44.373 h1.52
  text "REQUIRED" at 334.657,40.707 h1.52
  text "BARE BOARD ELEC. TEST:" at 289.769,40.634 h1.52
  text "NONE" at 322.935,40.634 h1.52
  text "X" at 331.66,40.634 h1.52
  text "PER ORDER" at 349.693,40.634 h1.52
  text "XX MIL VIAS REQUIRE NON-CONDUCTIVE FILL AND PLANARIZE" at 294.04,35.428 h1.5
  text "XX MIL VIAS REQUIRE CONDUCTIVE FILL AND PLANARIZE" at 294.243,32.787 h1.52
  text "OUTER XX MIL TRACES REQUIRE 50 OHM SINGLE-ENDED IMPEDANCE" at 294.218,28.637 h1.47
  text "LAYER 2 & 3 (INNER LAYERS) XX MIL WIDE, XX MIL SPACE / TRACES REQUIRE 100 OHM DIFFERENTIAL IMPEDANCE" at 294.015,22.65 h1.52
  text ".Layer_Name" at 14.656,-21.806 h1.52
M11 Gerber Information:
  lines w0.254: -7.417,-23.626 160.223,-23.626 ; -7.417,-18.462 160.274,-18.462 ; -7.417,-13.297 -7.417,-28.791 94.31,-28.791 160.274,-28.791 160.274,-13.297 -7.404,-13.297 -7.404,-28.791 32.614,-28.791 ; 55.194,-28.791 55.194,-13.297 ; 87.376,-18.462 87.376,-13.297 ; 108.712,-18.462 108.712,-13.297 ; 124.511,-28.956 124.511,-23.804
  text "ALL ARTWORK VIEWED FROM TOP SIDE" at -5.804,-16.654 h1.52
  text "BOARD #:" at 57.099,-16.654 h1.52
  text ".PRJ_Number" at 70.955,-16.654 h1.52
  text "REV:" at 92.405,-16.654 h1.52
  text ".PCB_Rev" at 99.809,-16.654 h1.52
  text "SVN REV:" at 113.69,-16.654 h1.52
  text ".VersionControl_RevNumber" at 126.543,-16.654 h1.52
  text "LAYER NAME =" at -5.804,-21.806 h1.52
  text "TID #:" at 57.099,-21.819 h1.52
  text ".TID" at 70.955,-21.819 h1.52
  text "PLOT NAME =" at -5.804,-27.034 h1.52
  text ".plot_File_Name" at 14.656,-27.034 h1.52
  text "GENERATED    :" at 57.15,-27.034 h1.52
  text ".Print_Date" at 79.235,-27.034 h1.52
  text ".Print_Time" at 97.752,-27.034 h1.52
  text "TEXAS INSTRUMENTS" at 129.87,-27.034 h1.52
M12 Stackup:
  drawing of 529 lines, arcs and shapes, not listed
  text "Layer" at 249.469,200.023 h1.52
  text "Name" at 259.88,200.023 h1.52
  text "Material" at 293.653,200.023 h1.52
  text "Thickness" at 308.889,200.023 h1.52
  text "Constant" at 325.395,200.023 h1.52
  text "Board Layer Stack" at 339.869,200.023 h1.52
  text "Top Overlay" at 259.88,196.975 h1.52
  text "Top Solder" at 259.88,193.927 h1.52
  text "SM-001" at 293.653,193.927 h1.52
  text "1.00mil" at 308.889,193.927 h1.52
  text "4" at 325.395,193.927 h1.52
  text "Top Surface Finish" at 259.88,190.879 h1.52
  text "PbSn" at 293.653,190.879 h1.52
  text "0.79mil" at 308.889,190.879 h1.52
  text "1" at 249.469,187.831 h1.52
  text "Top Layer" at 259.88,187.831 h1.52
  text "CF-005" at 293.653,187.831 h1.52
  text "2.76mil" at 308.889,187.831 h1.52
  text "Dielectric 1" at 259.88,184.783 h1.52
  text "Core-036" at 293.653,184.783 h1.52
  text "20.00mil" at 308.889,184.783 h1.52
  text "4.6" at 325.395,184.783 h1.52
  text "Dielectric 2" at 259.88,181.735 h1.52
  text "PP-003" at 293.653,181.735 h1.52
  text "2.30mil" at 308.889,181.735 h1.52
  text "3.9" at 325.395,181.735 h1.52
  text "2" at 249.469,178.687 h1.52
  text "Int1 (Sign)" at 259.88,178.687 h1.52
  text "CF-005" at 293.653,178.687 h1.52
  text "2.76mil" at 308.889,178.687 h1.52
  text "Dielectric 3" at 259.88,175.639 h1.52
  text "Core-022" at 293.653,175.639 h1.52
  text "7.00mil" at 308.889,175.639 h1.52
  text "4.3" at 325.395,175.639 h1.52
  text "3" at 249.469,172.591 h1.52
  text "Int2 (Sign)" at 259.88,172.591 h1.52
  text "CF-005" at 293.653,172.591 h1.52
  text "2.76mil" at 308.889,172.591 h1.52
  text "Dielectric 4" at 259.88,169.543 h1.52
  text "PP-010" at 293.653,169.543 h1.52
  text "3.40mil" at 308.889,169.543 h1.52
  text "4" at 325.395,169.543 h1.52
  text "Dielectric 5" at 259.88,166.495 h1.52
  text "PP-010" at 293.653,166.495 h1.52
  text "3.40mil" at 308.889,166.495 h1.52
  text "4" at 325.395,166.495 h1.52
  text "4" at 249.469,163.447 h1.52
  text "Int3 (Sign)" at 259.88,163.447 h1.52
  text "CF-005" at 293.653,163.447 h1.52
  text "2.76mil" at 308.889,163.447 h1.52
  text "Dielectric 6" at 259.88,160.399 h1.52
  text "Core-022" at 293.653,160.399 h1.52
  text "7.00mil" at 308.889,160.399 h1.52
  text "4.3" at 325.395,160.399 h1.52
  text "5" at 249.469,157.351 h1.52
  text "Int4 (Sign)" at 259.88,157.351 h1.52
  text "CF-005" at 293.653,157.351 h1.52
  text "2.76mil" at 308.889,157.351 h1.52
  text "Dielectric 7" at 259.88,154.303 h1.52
  text "PP-003" at 293.653,154.303 h1.52
  text "2.30mil" at 308.889,154.303 h1.52
  text "3.9" at 325.395,154.303 h1.52
  text "Dielectric 8" at 259.88,151.255 h1.52
  text "Core-036" at 293.653,151.255 h1.52
  text "20.00mil" at 308.889,151.255 h1.52
  text "4.6" at 325.395,151.255 h1.52
  text "6" at 249.469,148.207 h1.52
  text "Bottom Layer" at 259.88,148.207 h1.52
  text "CF-005" at 293.653,148.207 h1.52
  text "2.76mil" at 308.889,148.207 h1.52
  text "Bottom Surface Finish" at 259.88,145.159 h1.52
  text "PbSn" at 293.653,145.159 h1.52
  text "0.79mil" at 308.889,145.159 h1.52
  text "Bottom Solder" at 259.88,142.111 h1.52
  text "SM-001" at 293.653,142.111 h1.52
  text "1.00mil" at 308.889,142.111 h1.52
  text "4" at 325.395,142.111 h1.52
  text "Bottom Overlay" at 259.88,139.063 h1.52
  text ".Layer_Name" at 14.656,-21.806 h1.52
M13 Component Bodies Top:
  text ".Layer_Name" at 14.656,-21.806 h1.52
M14 Component Bodies Bottom:
  text ".Layer_Name" at 14.656,-21.806 h1.52
M15 Courtyards Top:
  text ".Layer_Name" at 14.656,-21.806 h1.52
M16 Courtyards Bottom:
  text ".Layer_Name" at 14.656,-21.806 h1.52
Drill Drawing:
  circle w0.254: c136.238,80.415 r0.702
  lines w0.254: 135.537,74.802 136.94,74.802 136.238,73.398 135.537,74.802 ; 135.537,76.556 136.94,76.556 136.94,77.959 135.537,77.959 135.537,76.556 ; 135.537,83.222 135.888,83.222 136.238,82.871 136.589,83.222 136.94,83.222 136.589,83.573 136.94,83.924 136.589,83.924 136.238,84.275 135.888,83.924 135.537,83.924 135.888,83.573 135.537,83.222
  lines w0.305: 134.264,72.451 216.344,72.451 ; 134.264,85.082 216.344,85.082 ; 142.846,69.293 142.846,88.24 ; 151.279,69.293 151.279,88.24 ; 167.448,69.293 167.448,88.24 ; 174.03,69.293 174.03,88.24 ; 183.559,69.293 183.559,88.24 ; 201.957,69.293 201.957,88.24 ; 134.264,69.293 216.344,69.293 216.344,88.24 134.264,88.24 134.264,69.293
  text "Symbol" at 136.159,86.029 h1.83
  text "Quantity" at 143.793,86.029 h1.83
  text "Finished Hole Size" at 152.226,86.029 h1.83
  text "Plated" at 168.395,86.029 h1.83
  text "Hole Type" at 174.977,86.029 h1.83
  text "Drill Layer Pair" at 184.506,86.029 h1.83
  text "Hole Tolerance" at 202.904,86.029 h1.83
  text "12" at 143.793,82.871 h1.52
  text "7.87mil (0.200mm)" at 152.226,82.871 h1.52
  text "PTH" at 168.395,82.871 h1.52
  text "Round" at 174.977,82.871 h1.52
  text "Top Layer - Bottom Layer" at 184.506,82.871 h1.52
  text "20" at 143.793,79.714 h1.52
  text "12.60mil (0.320mm)" at 152.226,79.714 h1.52
  text "PTH" at 168.395,79.714 h1.52
  text "Round" at 174.977,79.714 h1.52
  text "(Mixed)" at 184.506,79.714 h1.52
  text "8" at 143.793,76.556 h1.52
  text "27.56mil (0.700mm)" at 152.226,76.556 h1.52
  text "PTH" at 168.395,76.556 h1.52
  text "Round" at 174.977,76.556 h1.52
  text "Top Layer - Bottom Layer" at 184.506,76.556 h1.52
  text "8" at 143.793,73.398 h1.52
  text "29.53mil (0.750mm)" at 152.226,73.398 h1.52
  text "PTH" at 168.395,73.398 h1.52
  text "Round" at 174.977,73.398 h1.52
  text "Top Layer - Bottom Layer" at 184.506,73.398 h1.52
  text "48 Total" at 143.793,70.241 h1.52
  text ".Layer_Name" at 14.656,-21.806 h1.52
M17 Embedded Cavity:
  text ".Layer_Name" at 14.656,-21.806 h1.52
M18 Embedded Assembly:
  text ".Layer_Name" at 14.656,-21.806 h1.52
M19 Embedded Keepout:
  text ".Layer_Name" at 14.656,-21.806 h1.52

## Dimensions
0,-10.16 to 25.4,-10.16 on M2 Board Dimensions
0,0 to -0.5,22.305 on M2 Board Dimensions
35,4.252 to 0,-0.25 on M2 Board Dimensions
